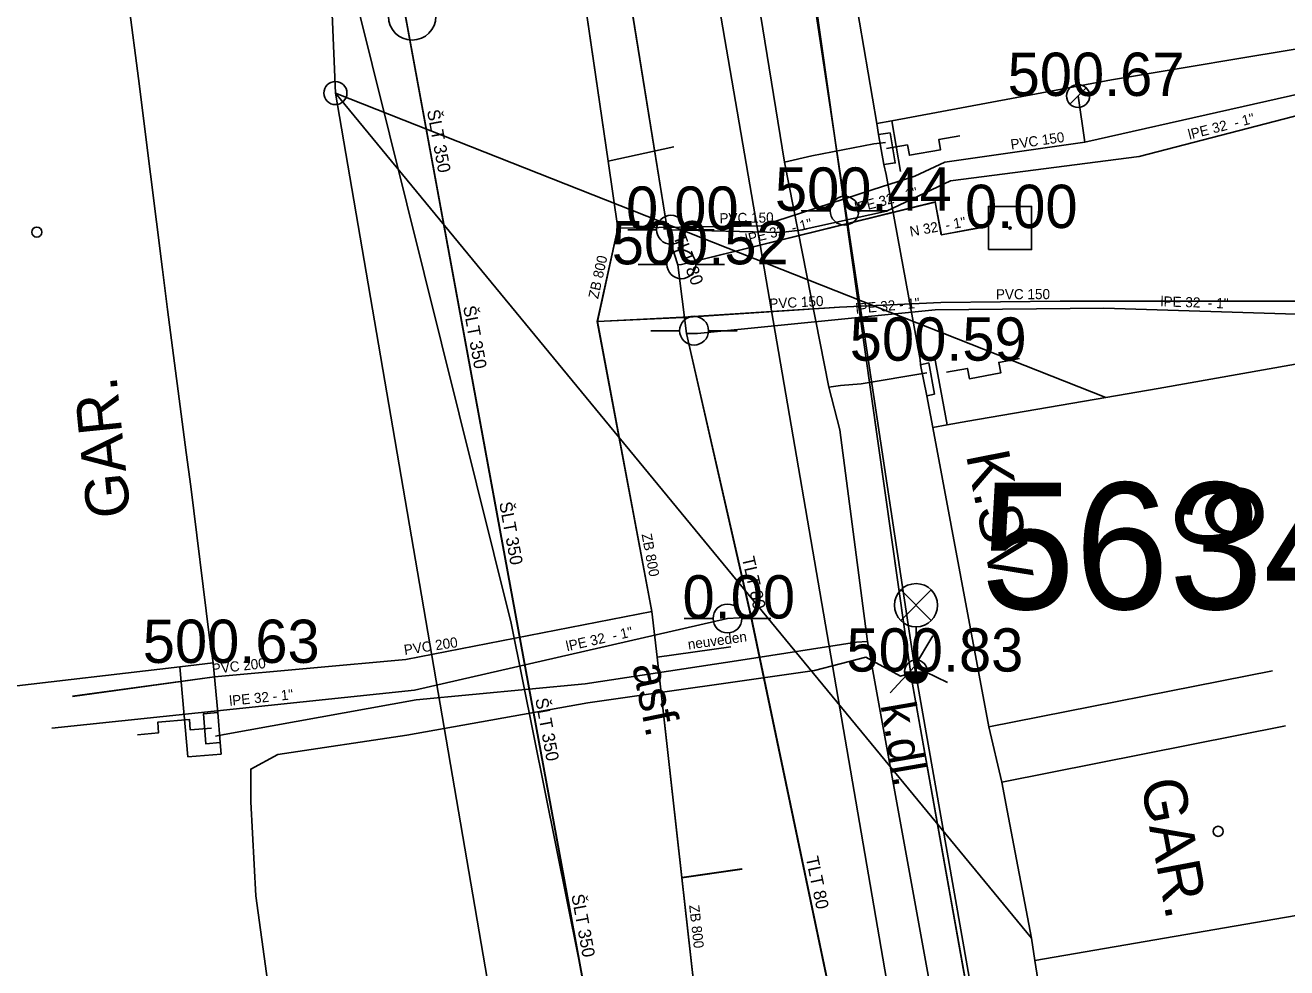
# Model space of a CAD drawing. Extents: x -669642 to -669119, y -1131006 to -1130466.
# Drawn here: x -669411.93 to -669390.05, y -1130737.23 to -1130720.88 of the extents above; entities that cross this region are included whole.
import ezdxf

# ---------------------------------------------------------------- set-up
doc = ezdxf.new("R2010")
doc.units = 0
for name, color, linetype in [('G_Bod_tecka', 7, 'Continuous'), ('G_Bod_vyska', 7, 'Continuous'), ('G_Bodove_pole', 7, 'Continuous'), ('G_Budovy-znacky', 7, 'Continuous'), ('G_Budovy_Objekty', 7, 'Continuous'), ('G_Budovy_vstupy', 7, 'Continuous'), ('G_Cisla_orientacni', 7, 'Continuous'), ('G_Objekty_technicke', 7, 'Continuous'), ('G_Plochy_zpevnene', 7, 'Continuous'), ('G_Ploty', 7, 'Continuous'), ('G_Ploty_vstupy', 7, 'Continuous'), ('G_Popisy_objektu', 7, 'Continuous'), ('G_Popisy_povrchu', 7, 'Continuous'), ('G_Poznamky_odkaz', 7, 'Continuous'), ('G_Site-kanalizace', 7, 'Continuous'), ('G_Site-Rozvadece', 7, 'Continuous'), ('G_Site-Sachty_N', 7, 'Continuous'), ('G_Site-Sloupy', 7, 'Continuous'), ('G_Site-vodovod', 7, 'Continuous'), ('G_Z_ELsilove_nadz_kotovane', 7, 'Continuous'), ('G_Z_ELsilove_podz_kotovane', 7, 'Continuous'), ('G_Z_KANAL_podz_kotovane', 7, 'Continuous'), ('G_Z_PLYNY_podz_geodeticky', 7, 'Continuous'), ('G_Z_SPOJE_nadz_kotovane', 7, 'Continuous'), ('G_Z_VODA_podz_kotovane', 7, 'Continuous'), ('Vrstva 1', 7, 'Continuous'), ('Vrstva 12', 7, 'Continuous'), ('Vrstva 13', 7, 'Continuous'), ('Vrstva 25', 7, 'Continuous'), ('Vrstva 26', 7, 'Continuous'), ('Vrstva 3', 7, 'Continuous'), ('Vrstva 4', 7, 'Continuous'), ('Vrstva 5', 7, 'Continuous'), ('Vrstva 6', 7, 'Continuous')]:
    doc.layers.add(name, color=color, linetype=linetype)

msp = doc.modelspace()

# ---------------------------------------------------------------- linework, layer by layer
at = {"layer": 'G_Bod_tecka'}
for p, q in [((-669393.67, -1130722.11), (-669393.67, -1130722.11)), ((-669397.72, -1130724.1), (-669397.72, -1130724.1)), ((-669400.73, -1130724.43), (-669400.73, -1130724.43)), ((-669394.85, -1130724.4), (-669394.85, -1130724.4)), ((-669400.55, -1130725.03), (-669400.55, -1130725.03)), ((-669396.42, -1130726.7), (-669396.42, -1130726.7)), ((-669399.75, -1130731.17), (-669399.75, -1130731.17)), ((-669408.67, -1130731.94), (-669408.67, -1130731.94)), ((-669396.48, -1130732.09), (-669396.48, -1130732.09))]:
    msp.add_line(p, q, dxfattribs=at)
at = {"layer": 'G_Bodove_pole'}
msp.add_circle((-669405.22, -1130720.73), 0.412, dxfattribs=at)
at = {"layer": 'G_Budovy-znacky'}
for centre in [(-669411.73, -1130724.47), (-669391.24, -1130734.86)]:
    msp.add_circle(centre, 0.0875, dxfattribs=at)
at = {"layer": 'G_Budovy_Objekty'}
for p, q in [((-669397.16, -1130722.59), (-669398.09, -1130717.17)), ((-669390.74, -1130721.44), (-669389.14, -1130721.17)), ((-669393.09, -1130721.83), (-669396.9, -1130722.54)), ((-669409.95, -1130721.94), (-669409.86, -1130722.64)), ((-669396.9, -1130722.54), (-669397.16, -1130722.59)), ((-669409.55, -1130725.12), (-669409.46, -1130725.81)), ((-669393.19, -1130727.34), (-669392.28, -1130727.18)), ((-669395.58, -1130727.75), (-669395.94, -1130727.81)), ((-669395.94, -1130727.81), (-669396.19, -1130727.86)), ((-669395.22, -1130733.05), (-669396.19, -1130727.86)), ((-669409.14, -1130728.29), (-669409.06, -1130728.88)), ((-669408.67, -1130731.94), (-669408.74, -1130731.46)), ((-669414.77, -1130732.65), (-669409.25, -1130732.01)), ((-669409.25, -1130732.01), (-669408.67, -1130731.94)), ((-669390.3, -1130732.08), (-669395.22, -1130733.05)), ((-669390.07, -1130733.03), (-669394.99, -1130734.01)), ((-669394.9, -1130734.5), (-669394.99, -1130734.01)), ((-669389.48, -1130736.25), (-669394.42, -1130737.1)), ((-669394.42, -1130737.1), (-669394.48, -1130736.71)), ((-669393.33, -1130743.89), (-669394.42, -1130737.1))]:
    msp.add_line(p, q, dxfattribs=at)
at = {"layer": 'G_Budovy_vstupy'}
for p, q in [((-669409.95, -1130721.94), (-669410.26, -1130719.51)), ((-669393.09, -1130721.83), (-669390.74, -1130721.44)), ((-669409.55, -1130725.12), (-669409.86, -1130722.64)), ((-669409.14, -1130728.29), (-669409.46, -1130725.81)), ((-669389.9, -1130726.76), (-669392.28, -1130727.18)), ((-669393.19, -1130727.34), (-669395.58, -1130727.75)), ((-669408.74, -1130731.46), (-669409.06, -1130728.88)), ((-669394.9, -1130734.5), (-669394.48, -1130736.71))]:
    msp.add_line(p, q, dxfattribs=at)
at = {"layer": 'G_Objekty_technicke'}
for points in [[(-669396.745, -1130730.675), (-669396.215, -1130731.205)], [(-669396.745, -1130731.205), (-669396.215, -1130730.675)], [(-669396.48, -1130732.09), (-669396.48, -1130731.315)]]:
    msp.add_lwpolyline(points, dxfattribs=at)
for centre, radius in [((-669396.48, -1130730.94), 0.375), ((-669396.48, -1130732.09), 0.2)]:
    msp.add_circle(centre, radius, dxfattribs=at)
for radius in [0.18, 0.16, 0.14, 0.12, 0.1, 0.08, 0.06, 0.04, 0.02]:
    msp.add_arc((-669396.48, -1130732.09), radius, 180, 0, dxfattribs=at)
at = {"layer": 'G_Plochy_zpevnene'}
msp.add_line((-669396.99, -1130737.43), (-669400.42, -1130717.5), dxfattribs=at)
for points in [[(-669407.42, -1130715.5), (-669403.5, -1130731.25)], [(-669403.5, -1130731.25), (-669400.19, -1130747.71)]]:
    msp.add_lwpolyline(points, dxfattribs=at)
at = {"layer": 'G_Ploty'}
for p, q in [((-669396.75, -1130723.42), (-669396.9, -1130722.54)), ((-669397, -1130723.47), (-669397.04, -1130723.3)), ((-669395.94, -1130727.81), (-669396.16, -1130726.63)), ((-669396.4, -1130726.77), (-669396.41, -1130726.68)), ((-669396.19, -1130727.86), (-669396.29, -1130727.31)), ((-669409.25, -1130732.01), (-669409.11, -1130733.57)), ((-669408.67, -1130731.94), (-669408.59, -1130732.8)), ((-669408.55, -1130733.32), (-669408.53, -1130733.52)), ((-669408.53, -1130733.52), (-669409.11, -1130733.57))]:
    msp.add_line(p, q, dxfattribs=at)
msp.add_lwpolyline([(-669397.13, -1130722.78), (-669397.16, -1130722.59)], dxfattribs=at)
at = {"layer": 'G_Ploty_vstupy'}
for p, q in [((-669397, -1130723.47), (-669396.41, -1130726.68)), ((-669395.22, -1130733.05), (-669394.99, -1130734.01))]:
    msp.add_line(p, q, dxfattribs=at)
at = {"layer": 'G_Site-kanalizace'}
msp.add_lwpolyline([(-669393.529, -1130721.969), (-669393.67, -1130722.11), (-669393.812, -1130722.252)], dxfattribs=at)
msp.add_circle((-669393.67, -1130722.111), 0.2, dxfattribs=at)
at = {"layer": 'G_Site-Rozvadece'}
for points in [[(-669397.13, -1130722.78), (-669396.93, -1130722.75), (-669396.84, -1130723.27), (-669397.04, -1130723.3)], [(-669396.4, -1130726.77), (-669396.29, -1130727.31), (-669396.16, -1130727.28), (-669396.26, -1130726.74)], [(-669408.59, -1130732.8), (-669408.84, -1130732.82), (-669408.8, -1130733.34), (-669408.55, -1130733.32)]]:
    msp.add_lwpolyline(points, close=True, dxfattribs=at)
for points in [[(-669396.99, -1130723.02), (-669396.628, -1130722.958), (-669396.596, -1130723.138), (-669396.053, -1130723.044), (-669396.083, -1130722.864), (-669395.72, -1130722.8)], [(-669395.95, -1130726.9), (-669395.588, -1130726.833), (-669395.554, -1130727.013), (-669395.012, -1130726.911), (-669395.044, -1130726.731), (-669394.683, -1130726.662)], [(-669408.7, -1130733.07), (-669409.067, -1130733.101), (-669409.083, -1130732.919), (-669409.633, -1130732.968), (-669409.618, -1130733.15), (-669409.984, -1130733.184)]]:
    msp.add_lwpolyline(points, dxfattribs=at)
at = {"layer": 'G_Site-Sachty_N'}
msp.add_lwpolyline([(-669395.225, -1130724.775), (-669394.475, -1130724.775), (-669394.475, -1130724.025), (-669395.225, -1130724.025)], close=True, dxfattribs=at)
msp.add_circle((-669394.85, -1130724.4), 0.02, dxfattribs=at)
at = {"layer": 'G_Site-Sloupy'}
msp.add_circle((-669406.55, -1130722.06), 0.2, dxfattribs=at)
at = {"layer": 'G_Site-vodovod'}
for points in [[(-669397.97, -1130724.1), (-669398.47, -1130724.1)], [(-669397.47, -1130724.1), (-669396.97, -1130724.1)], [(-669400.98, -1130724.43), (-669401.48, -1130724.43)], [(-669400.48, -1130724.43), (-669399.98, -1130724.43)], [(-669400.8, -1130725.03), (-669401.3, -1130725.03)], [(-669400.3, -1130725.03), (-669399.8, -1130725.03)], [(-669400.58, -1130726.18), (-669401.08, -1130726.18)], [(-669400.08, -1130726.18), (-669399.58, -1130726.18)], [(-669400, -1130731.17), (-669400.5, -1130731.17)], [(-669399.5, -1130731.17), (-669399, -1130731.17)]]:
    msp.add_lwpolyline(points, dxfattribs=at)
for centre in [(-669397.72, -1130724.1), (-669400.73, -1130724.43), (-669400.55, -1130725.03), (-669400.33, -1130726.18), (-669399.75, -1130731.17)]:
    msp.add_circle(centre, 0.25, dxfattribs=at)
at = {"layer": 'G_Z_ELsilove_nadz_kotovane'}
for points in [[(-669400.027, -1130708.65), (-669396.504, -1130732)], [(-669396.504, -1130732), (-669396.186, -1130731.472)], [(-669396.504, -1130732), (-669396.928, -1130732.46)], [(-669396.504, -1130732), (-669391.98, -1130757.716), (-669387.149, -1130787.013)], [(-669396.504, -1130732), (-669395.932, -1130732.282)]]:
    msp.add_lwpolyline(points, dxfattribs=at)
at = {"layer": 'G_Z_ELsilove_podz_kotovane'}
for points in [[(-669397.44, -1130624.27), (-669398.48, -1130651.54), (-669400.06, -1130690.34), (-669400.27, -1130706.05), (-669396.56, -1130732.21), (-669391.83, -1130758.66)], [(-669396.48, -1130732.09), (-669396.75, -1130732.17), (-669397.35, -1130731.84), (-669398.24, -1130732.07), (-669402.17, -1130732.63), (-669405.31, -1130733.19), (-669407.55, -1130733.53), (-669408.02, -1130733.78), (-669408.02, -1130734.35), (-669407.93, -1130735.98), (-669407.56, -1130738.67), (-669407.91, -1130739.04), (-669408.01, -1130739.07)]]:
    msp.add_lwpolyline(points, dxfattribs=at)
at = {"layer": 'G_Z_KANAL_podz_kotovane'}
for p, q in [((-669393.67, -1130722.11), (-669393.55, -1130722.91)), ((-669401.82, -1130723.24), (-669400.68, -1130722.99)), ((-669400.97, -1130731.84), (-669399.69, -1130731.66)), ((-669400.54, -1130735.66), (-669399.5, -1130735.51))]:
    msp.add_line(p, q, dxfattribs=at)
for points in [[(-669394.69, -1130773.67), (-669395.62, -1130769.37), (-669397.4, -1130761.18), (-669397.96, -1130758.61), (-669398.24, -1130756.09), (-669399.58, -1130744.19), (-669400.54, -1130735.66), (-669400.97, -1130731.84), (-669401.06, -1130731.05), (-669402.01, -1130726.02), (-669401.65, -1130724.4), (-669401.82, -1130723.24), (-669402.71, -1130717.15), (-669403.44, -1130712.15), (-669404.01, -1130708.24), (-669405.38, -1130698.86), (-669405.54, -1130697.79)], [(-669388.34, -1130721.03), (-669388.36, -1130721.11), (-669388.52, -1130721.78), (-669393.55, -1130722.91), (-669395.98, -1130723.26), (-669396.5, -1130723.5), (-669397.24, -1130723.74), (-669399.16, -1130724.36), (-669401.65, -1130724.4)], [(-669402.01, -1130726.02), (-669400.52, -1130725.95), (-669397.81, -1130725.77), (-669396.05, -1130725.69), (-669393.98, -1130725.67), (-669391.22, -1130725.67), (-669389.53, -1130725.67), (-669389.3, -1130725.69), (-669389.13, -1130725.77), (-669388.3, -1130726.51)], [(-669411.11, -1130732.52), (-669408.65, -1130732.18), (-669405.33, -1130731.88), (-669401.06, -1130731.05)]]:
    msp.add_lwpolyline(points, dxfattribs=at)
at = {"layer": 'G_Z_PLYNY_podz_geodeticky'}
for points in [[(-669400.98, -1130689.56), (-669400.99, -1130709.56), (-669398.76, -1130723.26), (-669397.99, -1130727.16), (-669397.8, -1130727.9), (-669397.32, -1130731.57), (-669394.97, -1130744.51), (-669391.88, -1130762.42), (-669391.21, -1130766.34), (-669390.43, -1130771.32)], [(-669398.29, -1130723.15), (-669397.21, -1130722.94), (-669397.11, -1130722.93), (-669397.01, -1130722.92)], [(-669398.76, -1130723.26), (-669398.29, -1130723.15)], [(-669397.79, -1130727.13), (-669397.43, -1130727.1), (-669396.29, -1130726.91)], [(-669397.99, -1130727.16), (-669397.79, -1130727.13)], [(-669397.51, -1130731.58), (-669399.52, -1130731.89), (-669402.22, -1130732.3), (-669405.15, -1130732.58), (-669408.48, -1130733.18), (-669408.63, -1130733.21)], [(-669397.32, -1130731.57), (-669397.51, -1130731.58)]]:
    msp.add_lwpolyline(points, dxfattribs=at)
at = {"layer": 'G_Z_SPOJE_nadz_kotovane'}
for points in [[(-669408.34, -1130679.44), (-669406.55, -1130722.06)], [(-669406.55, -1130722.06), (-669400.29, -1130758.6), (-669393.51, -1130791.5)], [(-669406.55, -1130722.06), (-669394.48, -1130736.71)], [(-669406.55, -1130722.06), (-669393.19, -1130727.34)]]:
    msp.add_lwpolyline(points, dxfattribs=at)
at = {"layer": 'G_Z_VODA_podz_kotovane'}
msp.add_line((-669396.04, -1130724.52), (-669395.31, -1130724.38), dxfattribs=at)
for points in [[(-669387.02, -1130812.53), (-669389.23, -1130792.08), (-669391, -1130779.42), (-669391.97, -1130772.22), (-669392.06, -1130771.92), (-669391.97, -1130771.16), (-669393.13, -1130764.98), (-669393.69, -1130761.37), (-669394.75, -1130753.04), (-669396.24, -1130745.91), (-669399.34, -1130731.13), (-669400.46, -1130726.23), (-669400.61, -1130725.04), (-669400.78, -1130724.52), (-669402.59, -1130713.28), (-669402.7, -1130712.61), (-669402.95, -1130701.47), (-669402.25, -1130693.89), (-669402.71, -1130680.24), (-669402.15, -1130669.87), (-669400.75, -1130656.95), (-669398.85, -1130641.75)], [(-669403.09, -1130650.73), (-669405.21, -1130670.54), (-669406.48, -1130689.47), (-669407.14, -1130697.84), (-669406.32, -1130715.38), (-669403.7, -1130729.64), (-669400.71, -1130745.88), (-669399.15, -1130753.32), (-669398.52, -1130755.36), (-669396.1, -1130756.91), (-669395.09, -1130760.49), (-669394.09, -1130765.4), (-669391.66, -1130786.81), (-669388.98, -1130811.25)], [(-669388.1, -1130720.99), (-669388.12, -1130721.04), (-669388.55, -1130722.11), (-669392.61, -1130723.16), (-669395.88, -1130723.58), (-669396.99, -1130724.11), (-669398.49, -1130724.44), (-669398.83, -1130724.48), (-669400.73, -1130724.43), (-669400.78, -1130724.52)], [(-669400.61, -1130725.04), (-669400.55, -1130725.03), (-669396.15, -1130723.95), (-669396.04, -1130724.52)], [(-669388.49, -1130726.51), (-669388.87, -1130726.1), (-669389.7, -1130725.9), (-669393.22, -1130725.79), (-669396.15, -1130725.82), (-669400.27, -1130726.23), (-669400.46, -1130726.23)], [(-669411.47, -1130733.07), (-669405.18, -1130732.41), (-669399.75, -1130731.17), (-669399.55, -1130731.16), (-669399.34, -1130731.13)]]:
    msp.add_lwpolyline(points, dxfattribs=at)
at = {"layer": 'Vrstva 1'}
msp.add_line((-669396.56, -1130732.21), (-669396.56, -1130732.21), dxfattribs=at)
at = {"layer": 'Vrstva 12'}
msp.add_line((-669393.67, -1130722.11), (-669393.55, -1130722.91), dxfattribs=at)
for points in [[(-669394.689, -1130773.674), (-669395.624, -1130769.369), (-669397.401, -1130761.182), (-669397.96, -1130758.61), (-669398.244, -1130756.087), (-669399.582, -1130744.192), (-669400.541, -1130735.664), (-669400.971, -1130731.838), (-669401.06, -1130731.05), (-669402.007, -1130726.018), (-669401.65, -1130724.4), (-669401.819, -1130723.242), (-669402.711, -1130717.147), (-669403.441, -1130712.15), (-669404.013, -1130708.242), (-669405.385, -1130698.862), (-669405.541, -1130697.793)], [(-669388.341, -1130721.031), (-669388.36, -1130721.11), (-669388.52, -1130721.78), (-669393.55, -1130722.91), (-669395.98, -1130723.26), (-669396.5, -1130723.5), (-669397.24, -1130723.74), (-669399.16, -1130724.36), (-669401.65, -1130724.4)], [(-669402.007, -1130726.018), (-669400.522, -1130725.946), (-669397.808, -1130725.771), (-669396.05, -1130725.692), (-669393.98, -1130725.668), (-669391.222, -1130725.667), (-669389.531, -1130725.67), (-669389.3, -1130725.69), (-669389.13, -1130725.77), (-669388.3, -1130726.51)], [(-669411.109, -1130732.518), (-669408.649, -1130732.181), (-669405.33, -1130731.88), (-669401.06, -1130731.05)]]:
    msp.add_lwpolyline(points, dxfattribs=at)
at = {"layer": 'Vrstva 13'}
for p, q in [((-669401.819, -1130723.242), (-669400.68, -1130722.99)), ((-669400.971, -1130731.838), (-669399.693, -1130731.659)), ((-669400.541, -1130735.664), (-669399.497, -1130735.515))]:
    msp.add_line(p, q, dxfattribs=at)
at = {"layer": 'Vrstva 25'}
msp.add_line((-669396.043, -1130724.517), (-669395.305, -1130724.383), dxfattribs=at)
at = {"layer": 'Vrstva 26'}
for points in [[(-669387.019, -1130812.528), (-669389.231, -1130792.082), (-669391.001, -1130779.42), (-669391.97, -1130772.22), (-669392.06, -1130771.92), (-669391.97, -1130771.16), (-669393.133, -1130764.977), (-669393.689, -1130761.37), (-669394.75, -1130753.038), (-669396.244, -1130745.914), (-669399.343, -1130731.135), (-669400.461, -1130726.23), (-669400.612, -1130725.037), (-669400.78, -1130724.52), (-669402.594, -1130713.284), (-669402.695, -1130712.614), (-669402.948, -1130701.466), (-669402.247, -1130693.89), (-669402.705, -1130680.236), (-669402.147, -1130669.872), (-669400.746, -1130656.946), (-669398.853, -1130641.75)], [(-669403.087, -1130650.733), (-669405.214, -1130670.54), (-669406.476, -1130689.467), (-669407.14, -1130697.842), (-669406.32, -1130715.384), (-669403.695, -1130729.64), (-669400.705, -1130745.879), (-669399.153, -1130753.32), (-669398.519, -1130755.364), (-669396.099, -1130756.914), (-669395.09, -1130760.491), (-669394.091, -1130765.401), (-669391.664, -1130786.81), (-669388.978, -1130811.253)], [(-669388.1, -1130720.989), (-669388.12, -1130721.04), (-669388.55, -1130722.11), (-669392.61, -1130723.16), (-669395.88, -1130723.58), (-669396.99, -1130724.11), (-669398.49, -1130724.44), (-669398.83, -1130724.48), (-669400.73, -1130724.43), (-669400.78, -1130724.52)], [(-669400.612, -1130725.037), (-669400.55, -1130725.03), (-669396.147, -1130723.946), (-669396.043, -1130724.517)], [(-669388.491, -1130726.51), (-669388.871, -1130726.1), (-669389.701, -1130725.9), (-669393.221, -1130725.79), (-669396.15, -1130725.82), (-669400.271, -1130726.23), (-669400.461, -1130726.23)], [(-669411.47, -1130733.071), (-669405.18, -1130732.41), (-669399.75, -1130731.17), (-669399.55, -1130731.16), (-669399.343, -1130731.135)]]:
    msp.add_lwpolyline(points, dxfattribs=at)
at = {"layer": 'Vrstva 5'}
for p, q in [((-669400.27, -1130706.05), (-669396.56, -1130732.21)), ((-669396.56, -1130732.21), (-669400.27, -1130706.05)), ((-669396.56, -1130732.21), (-669391.83, -1130758.66)), ((-669391.83, -1130758.66), (-669396.56, -1130732.21))]:
    msp.add_line(p, q, dxfattribs=at)
at = {"layer": 'Vrstva 6'}
for p, q in [((-669400.73, -1130724.43), (-669400.73, -1130724.43)), ((-669400.55, -1130725.03), (-669400.55, -1130725.03)), ((-669400.271, -1130726.23), (-669400.271, -1130726.23)), ((-669399.75, -1130731.17), (-669399.75, -1130731.17))]:
    msp.add_line(p, q, dxfattribs=at)

# ---------------------------------------------------------------- texts
at = {"layer": 'G_Bod_vyska'}
for s, p in [('500.67', (-669394.891, -1130722.11)), ('500.44', (-669398.927, -1130724.1)), ('0.00', (-669401.51, -1130724.43)), ('0.00', (-669395.63, -1130724.4)), ('500.52', (-669401.757, -1130725.03)), ('500.59', (-669397.629, -1130726.7)), ('0.00', (-669400.53, -1130731.17)), ('500.63', (-669409.891, -1130731.94)), ('500.83', (-669397.687, -1130732.09))]:
    msp.add_text(s, height=0.75, dxfattribs=at).set_placement(p)
at = {"layer": 'G_Cisla_orientacni'}
msp.add_text('9', height=1.5, rotation=280.6017, dxfattribs=at).set_placement((-669392.055, -1130729.003))
at = {"layer": 'G_Popisy_objektu'}
for rotation, p in [(95.7832, (-669410.102, -1130729.39)), (280.6901, (-669392.585, -1130734.005))]:
    msp.add_text('GAR.', height=0.75, rotation=rotation, dxfattribs=at).set_placement(p)
at = {"layer": 'G_Popisy_povrchu'}
for s, rotation, p in [('asf.', 281.5374, (-669401.406, -1130731.989)), ('k.dl.', 279.7738, (-669397.099, -1130732.667))]:
    msp.add_text(s, height=0.6, rotation=rotation, dxfattribs=at).set_placement(p)
at = {"layer": 'G_Poznamky_odkaz'}
msp.add_text('K.SV.', height=0.75, rotation=281.1987, dxfattribs=at).set_placement((-669395.617, -1130728.331))
at = {"layer": 'Vrstva 3'}
for s, rotation, p in [('PVC 150', 8.1926, (-669394.827, -1130723.04)), ('PVC 150', 0.918, (-669399.888, -1130724.319)), ('ZB 800', 77.524, (-669401.995, -1130725.638)), ('PVC 150', 0.187, (-669395.095, -1130725.636)), ('PVC 150', 3.1289, (-669399.019, -1130725.801)), ('ZB 800', 280.6571, (-669401.241, -1130729.712)), ('neuveden', 7.9563, (-669400.426, -1130731.708)), ('PVC 200', 8.5341, (-669405.348, -1130731.803)), ('PVC 200', 6.3571, (-669408.684, -1130732.132)), ('ZB 800', 276.4231, (-669400.416, -1130736.144))]:
    msp.add_text(s, height=0.1755, rotation=rotation, dxfattribs=at).set_placement(p)
at = {"layer": 'Vrstva 4'}
for s, height, rotation, p in [('ŠLT 350', 0.2194, 280.41, (-669404.963, -1130722.365)), ('lPE 32  - 1"', 0.17551, 14.3939, (-669391.737, -1130722.868)), ('lPE 32 - 1"', 0.17551, 14.7142, (-669397.515, -1130724.139)), ('lPE 32  - 1"', 0.17551, 13.6987, (-669399.416, -1130724.68)), ('N 32  - 1"', 0.1755, 10.239, (-669396.573, -1130724.55)), ('TLT 80', 0.2194, 290.9695, (-669400.696, -1130724.547)), ('ŠLT 350', 0.2194, 280.41, (-669404.337, -1130725.766)), ('lPE 32 - 1"', 0.17551, 5.4161, (-669397.519, -1130725.888)), ('lPE 32  - 1"', 0.17551, 358.1762, (-669392.242, -1130725.758)), ('ŠLT 350', 0.2194, 280.41, (-669403.711, -1130729.166)), ('TLT 80', 0.2194, 282.8319, (-669399.502, -1130730.121)), ('lPE 32  - 1"', 0.17551, 12.739, (-669402.53, -1130731.739)), ('lPE 32 - 1"', 0.17551, 5.9809, (-669408.382, -1130732.685)), ('ŠLT 350', 0.2194, 280.41, (-669403.085, -1130732.567)), ('TLT 80', 0.2194, 281.8644, (-669398.394, -1130735.316)), ('ŠLT 350', 0.2194, 280.41, (-669402.459, -1130735.967))]:
    msp.add_text(s, height=height, rotation=rotation, dxfattribs=at).set_placement(p)
msp.add_text('5634', height=2.1939, dxfattribs=at).set_placement((-669395.357, -1130731.008))

doc.saveas('drawing.dxf')
